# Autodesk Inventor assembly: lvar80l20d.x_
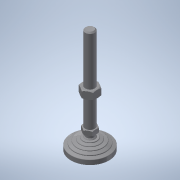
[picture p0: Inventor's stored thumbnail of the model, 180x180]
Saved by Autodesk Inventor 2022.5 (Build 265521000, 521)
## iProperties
Part Number: lvar80l20d.x_
Material: 一般
Document SubType Name: Assembly
Designer: ImaoCorp
Sending System: SOLIDWORKS 2017-2017317
MC: AMD64
MC_MODEL: Intel64 Family 6 Model 60 Stepping 3, GenuineIntel
OS: Windows_NT
FRU: Parasolid Version 29.0, build 201,  4-17-2017
FORMAT: text
GUISE: transmit
KEY: lvar80l20d
FILE: lvar80l20d.x_t
DATE: Mon Jul 01 18:15:05 2019
Author: ImaoCorp
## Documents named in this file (3)
- X:\14_SW2022-Inv2022\00_全2023-1023新製品(TCC)まで\l\lvar80l20d\LVAR80L20D.iam
- X:\14_SW2022-Inv2022\00_全2023-1023新製品(TCC)まで\l\lvar80l20d\lvar80l20d_01.ipt
- X:\14_SW2022-Inv2022\00_全2023-1023新製品(TCC)まで\l\lvar80l20d\lvar80l20d_02.ipt
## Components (2 placed, 2 different names)
1. lvar80l20d_01
2. lvar80l20d_02
